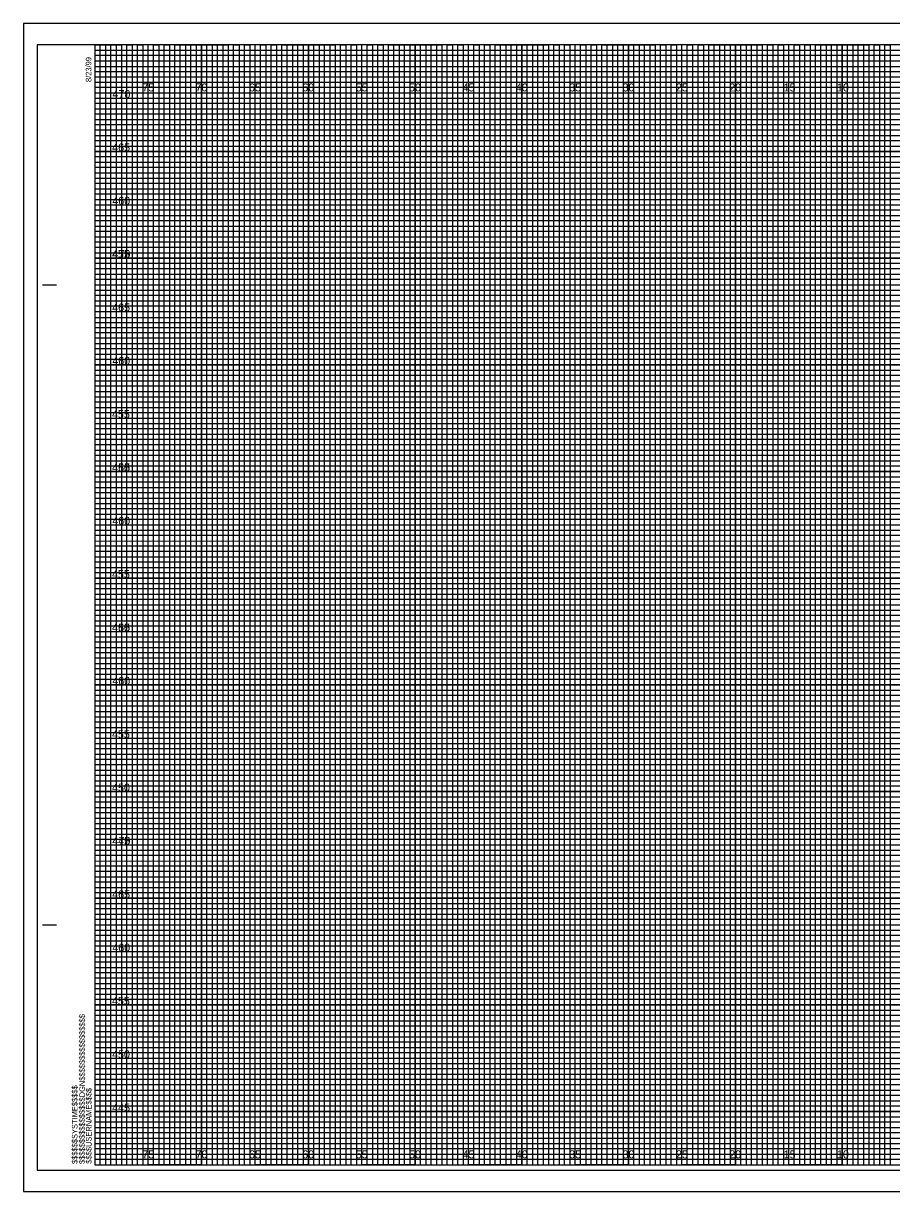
# Model space of a CAD drawing. Extents: x -7 to 162, y 328 to 437.
# Drawn here: x -6.7 to 74.6, y 327.5 to 437 of the extents above; entities that cross this region are included whole.
import ezdxf

# ---------------------------------------------------------------- set-up
doc = ezdxf.new("R2010")
doc.units = 0
for name, color, linetype in [('Prop XS Elevation Labels', 7, 'Continuous'), ('Prop XS Offset Labels', 7, 'Continuous'), ('Sheet Cross Section CELL', 7, 'Continuous'), ('Sheet Cross Section Grid Major CELL', 7, 'Continuous'), ('Sheet Cross Section Grid Middle CELL', 7, 'Continuous'), ('Sheet Cross Section Grid Minor 1 CELL', 7, 'Continuous'), ('Sheet Cross Section Grid Minor 2 CELL', 7, 'Continuous'), ('Sheet Cutting Line CELL', 7, 'Continuous'), ('Sheet DOT Grid CELL', 7, 'Continuous'), ('Sheet Plot Border Inside CELL', 7, 'Continuous'), ('Sheet Plot Border Outside CELL', 7, 'Continuous')]:
    doc.layers.add(name, color=color, linetype=linetype)

msp = doc.modelspace()

# ---------------------------------------------------------------- linework, layer by layer
at = {"layer": 'Sheet Cross Section CELL'}
for p, q in [((-4.9, 412.5), (-3.65, 412.5)), ((-4.85, 412.5), (-3.6, 412.5)), ((-4.9, 352.5), (-3.65, 352.5)), ((-4.85, 352.5), (-3.6, 352.5)), ((0, 330), (0, 330)), ((0, 330), (0, 330)), ((0, 330), (0, 330)), ((0, 330), (0, 330)), ((0, 330), (0, 330)), ((0, 330), (0, 330)), ((0, 330), (0, 330))]:
    msp.add_line(p, q, dxfattribs=at)
msp.add_lwpolyline([(160, 435), (0, 435), (0, 330), (160, 330)], close=True, dxfattribs=at)
at = {"layer": 'Sheet Cross Section Grid Major CELL'}
for p, q in [((5, 435), (0, 435)), ((5, 330), (5, 435)), ((15, 435), (10, 435)), ((10, 435), (10, 330)), ((15, 330), (15, 435)), ((25, 435), (20, 435)), ((20, 435), (20, 330)), ((25, 330), (25, 435)), ((35, 435), (30, 435)), ((30, 435), (30, 330)), ((35, 330), (35, 435)), ((45, 435), (40, 435)), ((40, 435), (40, 330)), ((45, 330), (45, 435)), ((55, 435), (50, 435)), ((50, 435), (50, 330)), ((55, 330), (55, 435)), ((65, 435), (60, 435)), ((60, 435), (60, 330)), ((65, 330), (65, 435)), ((75, 435), (70, 435)), ((70, 435), (70, 330)), ((10, 330), (5, 330)), ((20, 330), (15, 330)), ((30, 330), (25, 330)), ((40, 330), (35, 330)), ((50, 330), (45, 330)), ((60, 330), (55, 330)), ((70, 330), (65, 330))]:
    msp.add_line(p, q, dxfattribs=at)
for points in [[(0, 430), (160, 430), (160, 425), (0, 425)], [(0, 420), (160, 420), (160, 415), (0, 415)], [(0, 410), (160, 410), (160, 405), (0, 405)], [(0, 400), (160, 400), (160, 395), (0, 395)], [(0, 390), (160, 390), (160, 385), (0, 385)], [(0, 380), (160, 380), (160, 375), (0, 375)], [(0, 370), (160, 370), (160, 365), (0, 365)], [(0, 360), (160, 360), (160, 355), (0, 355)], [(0, 350), (160, 350), (160, 345), (0, 345)], [(0, 340), (160, 340), (160, 335), (0, 335)]]:
    msp.add_lwpolyline(points, dxfattribs=at)
at = {"layer": 'Sheet Cross Section Grid Middle CELL'}
for points in [[(0, 435), (2.5, 435), (2.5, 330), (7.5, 330), (7.5, 435), (12.5, 435), (12.5, 330), (17.5, 330), (17.5, 435), (22.5, 435), (22.5, 330), (27.5, 330), (27.5, 435), (32.5, 435), (32.5, 330), (37.5, 330), (37.5, 435), (42.5, 435), (42.5, 330), (47.5, 330), (47.5, 435), (52.5, 435), (52.5, 330), (57.5, 330), (57.5, 435), (62.5, 435), (62.5, 330), (67.5, 330), (67.5, 435), (72.5, 435), (72.5, 330), (77.5, 330)], [(0, 432.5), (137.5, 432.5)], [(0, 422.5), (160, 422.5), (160, 427.5), (0, 427.5)], [(0, 412.5), (160, 412.5), (160, 417.5), (0, 417.5)], [(0, 402.5), (160, 402.5), (160, 407.5), (0, 407.5)], [(0, 392.5), (160, 392.5), (160, 397.5), (0, 397.5)], [(0, 382.5), (160, 382.5), (160, 387.5), (0, 387.5)], [(0, 372.5), (160, 372.5), (160, 377.5), (0, 377.5)], [(0, 362.5), (160, 362.5), (160, 367.5), (0, 367.5)], [(0, 352.5), (160, 352.5), (160, 357.5), (0, 357.5)], [(0, 342.5), (160, 342.5), (160, 347.5), (0, 347.5)], [(0, 332.5), (160, 332.5), (160, 337.5), (0, 337.5)]]:
    msp.add_lwpolyline(points, dxfattribs=at)
at = {"layer": 'Sheet Cross Section Grid Minor 1 CELL'}
for p, q in [((0, 434.5), (130, 434.5)), ((130, 433.99), (0, 433.99)), ((0, 433.99), (0, 433.5)), ((0, 433.5), (130, 433.5)), ((130, 432.94), (0, 432.94)), ((0, 432.94), (0, 432)), ((0, 432), (160, 432))]:
    msp.add_line(p, q, dxfattribs=at)
for points in [[(0, 431.5), (135, 431.5), (160, 431.5), (160, 431), (0, 431)], [(0, 430.5), (160, 430.5), (160, 429.5), (0, 429.5)], [(0, 429), (160, 429), (160, 428.5), (0, 428.49)], [(0, 428), (160, 428), (160, 427), (0, 427)], [(0, 426.5), (160, 426.5), (160, 426), (0, 426)], [(0, 425.5), (160, 425.5), (160, 424.5), (0, 424.5)], [(0, 424), (160, 424), (160, 423.5), (0, 423.5)], [(0, 423), (160, 423), (160, 422), (0, 422)], [(0, 421.5), (160, 421.5), (160, 421), (0, 421)], [(0, 420.5), (160, 420.5), (160, 419.5), (0, 419.5)], [(0, 419), (160, 419), (160, 418.5), (0, 418.5)], [(0, 418), (160, 418), (160, 416.98), (160, 416.5), (160, 416), (0, 416)], [(0, 417), (160, 417), (160, 416.5), (0, 416.5)], [(0, 415.5), (160, 415.5), (160, 414.5), (0, 414.51)], [(0, 414.51), (160, 414.5), (160, 414), (0, 414)], [(0, 413.5), (160, 413.5), (160, 413), (0, 413)], [(0, 412), (160, 412), (160, 411.5), (0, 411.5)], [(0, 411), (160, 411), (160, 410.5), (0, 410.5)], [(-0.04, 409.44), (160, 409.44), (160, 408.94), (-0.04, 408.94)], [(0, 408.5), (160, 408.5), (160, 408), (0, 408)], [(0, 407), (160, 407), (160, 406.5), (0, 406.5)], [(0, 406), (160, 406), (160, 405.5), (0, 405.5)], [(0, 404.5), (160, 404.5), (160, 404), (0, 404)], [(0, 403.5), (160, 403.5), (160, 403), (0, 403)], [(0, 402), (160, 402), (160, 401.5), (0, 401.5)], [(0, 401), (160, 401), (160, 400.5), (0, 400.5)], [(0, 399.5), (160, 399.5), (160, 398.99), (0, 399)], [(0, 398.5), (160, 398.5), (160, 398), (0, 398)], [(0, 397), (160, 397), (160, 396.5), (0, 396.5)], [(0, 396), (160, 396), (160, 395.5), (0, 395.5)], [(0, 394.5), (160, 394.5), (160, 394), (0, 394)], [(0, 393.5), (160, 393.5), (160, 393), (0, 393)], [(0, 392), (160, 392), (160, 391.5), (0, 391.5)], [(0, 391), (160, 391), (160, 390.5), (0, 390.5)], [(0, 389.5), (160, 389.5), (160, 389), (0, 389)], [(0, 388.5), (160.03, 388.45), (160, 388), (0, 388)], [(0, 387), (160, 387), (160, 386.5), (0, 386.5)], [(0, 386), (160, 386), (160, 385.5), (0, 385.5)], [(0, 384.5), (160, 384.5), (160, 384), (0, 384)], [(0, 383.5), (160, 383.5), (160, 383), (0, 383)], [(0, 382), (160, 382), (160, 381.5), (0, 381.5)], [(0, 381), (160, 381), (160, 380.5), (0, 380.5)], [(0, 379.5), (160, 379.5), (160, 379), (0, 379)], [(0, 378.5), (160, 378.5), (160, 378), (0, 378)], [(0, 377), (160, 377), (160, 376.5), (0, 376.5)], [(0, 376), (160, 376), (160, 375.5), (0, 375.5)], [(0, 374.5), (160, 374.5), (160, 374), (0, 374)], [(0, 373.5), (160, 373.5), (160, 373), (0, 373)], [(0, 372), (160, 372), (160, 371.5), (0, 371.5)], [(0, 371), (160, 371), (160, 370.5), (0, 370.5)], [(0, 369.5), (160, 369.5), (160, 368.99), (0, 369)], [(0, 368.5), (160, 368.5), (160, 368), (0, 368)], [(0, 367), (160, 367), (160, 366.5), (0, 366.5)], [(0, 366), (160, 366), (160, 365.5), (0, 365.5)], [(0, 364.5), (160, 364.5), (160, 364), (0, 364)], [(0, 363.5), (160, 363.5), (160, 363), (0, 363)], [(0, 362), (160, 362), (160, 361.5), (0, 361.5)], [(0, 361), (160, 361), (160, 360.5), (0, 360.5)], [(0, 359.5), (160, 359.5), (160, 359), (0, 359)], [(0, 358.5), (160.03, 358.45), (160, 358), (0, 358)], [(0, 357), (160, 357), (160, 356.5), (0, 356.5)], [(0, 356), (160, 356), (160, 355.5), (0, 355.5)], [(0, 354.5), (160, 354.5), (160, 354), (0, 354)], [(0, 353.5), (160, 353.5), (160, 353), (0, 353)], [(0, 352), (160, 352), (160, 351.5), (0, 351.5)], [(0, 351), (160, 351), (160, 350.5), (0, 350.5)], [(0, 349.5), (160, 349.5), (160, 349), (0, 349)], [(0, 348.5), (160, 348.5), (160, 348), (0, 348)], [(0, 347), (160, 347), (160, 346.5), (0, 346.5)], [(0, 346), (160, 346), (160, 345.5), (0, 345.5)], [(0, 344.5), (160, 344.5), (160, 344), (0, 344)], [(0, 343.5), (160, 343.5), (160, 343), (0, 343)], [(0, 342), (160, 342), (160, 341.5), (0, 341.5)], [(0, 341), (160, 341), (160, 340.5), (0, 340.5)], [(0, 339.5), (160, 339.5), (160, 339), (0, 339)], [(0, 338.5), (160, 338.5), (160, 338), (0, 338)], [(0, 337), (160, 337), (160, 336.5), (0, 336.5)], [(0, 336), (160, 336), (160, 335.5), (0, 335.5)], [(0, 334.5), (160, 334.5), (160, 334), (0, 334)], [(0, 333.5), (160, 333.5), (160, 333), (0, 333)], [(0, 332), (160, 332), (160, 331.5), (0, 331.5)], [(0, 331), (160, 331), (160, 330.5), (0, 330.5)]]:
    msp.add_lwpolyline(points, dxfattribs=at)
at = {"layer": 'Sheet Cross Section Grid Minor 2 CELL'}
for points in [[(0, 330), (0.5, 330), (0.5, 435), (1, 435), (1, 330)], [(1, 330), (1.5, 330), (1.5, 435), (2, 435), (2, 330)], [(2.5, 330), (3, 330), (3, 435), (3.5, 435), (3.5, 330)], [(3.5, 330), (4, 330), (4, 435), (4.5, 435), (4.5, 330)], [(5, 330), (5.5, 330), (5.5, 435), (6, 435), (6, 330)], [(6, 330), (6.5, 330), (6.5, 435), (7, 435), (7, 330)], [(7.5, 330), (8, 330), (8, 435), (8.5, 435), (8.5, 330)], [(8.5, 330), (9, 330), (9, 435), (9.5, 435), (9.5, 330)], [(10, 330), (10.5, 330), (10.5, 435), (11, 435), (11, 330)], [(11, 330), (11.5, 330), (11.5, 435), (12, 435), (12, 330)], [(12.5, 330), (13, 330), (13, 435), (13.5, 435), (13.5, 330)], [(13.5, 330), (14, 330), (14, 435), (14.5, 435), (14.5, 330)], [(15, 330), (15.5, 330), (15.5, 435), (16, 435), (16, 330)], [(16, 330), (16.5, 330), (16.5, 435), (17, 435), (17, 330)], [(17.5, 330), (18, 330), (18, 435), (18.5, 435), (18.5, 330)], [(18.5, 330), (19, 330), (19, 435), (19.5, 435), (19.5, 330)], [(20, 330), (20.5, 330), (20.5, 435), (21, 435), (21, 330)], [(21, 330), (21.5, 330), (21.5, 435), (22, 435), (22, 330)], [(22.5, 330), (23, 330), (23, 435), (23.5, 435), (23.5, 330)], [(23.5, 330), (24, 330), (24, 435), (24.5, 435), (24.5, 330)], [(25, 330), (25.5, 330), (25.5, 435), (26, 435), (26, 330)], [(26, 330), (26.5, 330), (26.5, 435), (27, 435), (27, 330)], [(27.5, 330), (28, 330), (28, 435), (28.5, 435), (28.5, 330)], [(28.5, 330), (29, 330), (29, 435), (29.5, 435), (29.5, 330)], [(30, 330), (30.5, 330), (30.5, 435), (31, 435), (31, 330)], [(31, 330), (31.5, 330), (31.5, 435), (32, 435), (32, 330)], [(32.5, 330), (33, 330), (33, 435), (33.5, 435), (33.5, 330)], [(33.5, 330), (34, 330), (34, 435), (34.5, 435), (34.5, 330)], [(35, 330), (35.5, 330), (35.5, 435), (36, 435), (36, 330)], [(36, 330), (36.5, 330), (36.5, 435), (37, 435), (37, 330)], [(37.5, 330), (38, 330), (38, 435), (38.5, 435), (38.5, 330)], [(38.5, 330), (39, 330), (39, 435), (39.5, 435), (39.5, 330)], [(40, 330), (40.5, 330), (40.5, 435), (41, 435), (41, 330)], [(41, 330), (41.5, 330), (41.5, 435), (42, 435), (42, 330)], [(42.5, 330), (43, 330), (43, 435), (43.5, 435), (43.5, 330)], [(43.5, 330), (44, 330), (44, 435), (44.5, 435), (44.5, 330)], [(45, 330), (45.5, 330), (45.5, 435), (46, 435), (46, 330)], [(46, 330), (46.5, 330), (46.5, 435), (47, 435), (47, 330)], [(47.5, 330), (48, 330), (48, 435), (48.5, 435), (48.5, 330)], [(48.5, 330), (49, 330), (49, 435), (49.5, 435), (49.5, 330)], [(50, 330), (50.5, 330), (50.5, 435), (51, 435), (51, 330)], [(51, 330), (51.5, 330), (51.5, 435), (52, 435), (52, 330)], [(52.5, 330), (53, 330), (53, 435), (53.5, 435), (53.5, 330)], [(53.5, 330), (54, 330), (54, 435), (54.5, 435), (54.5, 330)], [(55, 330), (55.5, 330), (55.5, 435), (56, 435), (56, 330)], [(56, 330), (56.5, 330), (56.5, 435), (57, 435), (57, 330)], [(57.5, 330), (58, 330), (58, 435), (58.5, 435), (58.5, 330)], [(58.5, 330), (59, 330), (59, 435), (59.5, 435), (59.5, 330)], [(60, 330), (60.5, 330), (60.5, 435), (61, 435), (61, 330)], [(61, 330), (61.5, 330), (61.5, 435), (62, 435), (62, 330)], [(62.5, 330), (63, 330), (63, 435), (63.5, 435), (63.5, 330)], [(63.5, 330), (64, 330), (64, 435), (64.5, 435), (64.5, 330)], [(65, 330), (65.5, 330), (65.5, 435), (66, 435), (66, 330)], [(66, 330), (66.5, 330), (66.5, 435), (67, 435), (67, 330)], [(67.5, 330), (68, 330), (68, 435), (68.5, 435), (68.5, 330)], [(68.5, 330), (69, 330), (69, 435), (69.5, 435), (69.5, 330)], [(70, 330), (70.5, 330), (70.5, 435), (71, 435), (71, 330)], [(71, 330), (71.5, 330), (71.5, 435), (72, 435), (72, 330)], [(72.5, 330), (73, 330), (73, 435), (73.5, 435), (73.5, 330)], [(73.5, 330), (74, 330), (74, 435), (74.5, 435), (74.5, 330)]]:
    msp.add_lwpolyline(points, dxfattribs=at)
at = {"layer": 'Sheet Cutting Line CELL'}
for p, q in [((161.65, 437), (-6.7, 437)), ((-6.7, 437), (-6.7, 327.5)), ((-6.7, 327.5), (161.65, 327.5))]:
    msp.add_line(p, q, dxfattribs=at)
at = {"layer": 'Sheet DOT Grid CELL'}
for p, q in [((5, 330), (5, 435)), ((10, 330), (10, 435)), ((15, 330), (15, 435)), ((20, 330), (20, 435)), ((25, 330), (25, 435)), ((30, 330), (30, 435)), ((35, 330), (35, 435)), ((40, 330), (40, 435)), ((45, 330), (45, 435)), ((50, 330), (50, 435)), ((55, 330), (55, 435)), ((60, 330), (60, 435)), ((65, 330), (65, 435)), ((70, 330), (70, 435)), ((0, 430), (160, 430)), ((0, 425), (160, 425)), ((0, 420), (160, 420)), ((0, 415), (160, 415)), ((0, 410), (160, 410)), ((0, 405), (160, 405)), ((0, 400), (160, 400)), ((0, 395), (160, 395)), ((0, 390), (160, 390)), ((0, 385), (160, 385)), ((0, 380), (160, 380)), ((0, 375), (160, 375)), ((0, 370), (160, 370)), ((0, 365), (160, 365)), ((0, 360), (160, 360)), ((0, 355), (160, 355)), ((0, 350), (160, 350)), ((0, 345), (160, 345)), ((0, 340), (160, 340)), ((0, 335), (160, 335))]:
    msp.add_line(p, q, dxfattribs=at)
at = {"layer": 'Sheet Plot Border Inside CELL'}
msp.add_lwpolyline([(-5.4, 329.5), (161.2, 329.5), (161.2, 435), (-5.4, 435)], close=True, dxfattribs=at)
at = {"layer": 'Sheet Plot Border Outside CELL'}
msp.add_lwpolyline([(-6.7, 327.5), (161.65, 327.5), (161.65, 437), (-6.7, 437)], close=True, dxfattribs=at)

# ---------------------------------------------------------------- texts
at = {"layer": 'Prop XS Elevation Labels'}
for s, p in [('470', (1.65, 430)), ('465', (1.62, 425)), ('460', (1.63, 420)), ('455', (1.6, 415)), ('470', (1.65, 415)), ('465', (1.62, 410)), ('460', (1.63, 405)), ('455', (1.6, 400)), ('450', (1.61, 395)), ('465', (1.62, 395)), ('460', (1.63, 390)), ('455', (1.6, 385)), ('450', (1.61, 380)), ('465', (1.62, 380)), ('460', (1.63, 375)), ('455', (1.6, 370)), ('450', (1.61, 365)), ('445', (1.62, 360)), ('470', (1.65, 360)), ('465', (1.62, 355)), ('460', (1.63, 350)), ('455', (1.6, 345)), ('450', (1.61, 340)), ('445', (1.62, 335))]:
    msp.add_text(s, height=0.75, dxfattribs=at).set_placement(p)
at = {"layer": 'Prop XS Offset Labels'}
for s, p in [('75', (4.44, 430.62)), ('70', (9.43, 430.62)), ('65', (14.44, 430.62)), ('60', (19.43, 430.62)), ('55', (24.44, 430.62)), ('50', (29.43, 430.62)), ('45', (34.44, 430.62)), ('40', (39.43, 430.62)), ('35', (44.44, 430.62)), ('30', (49.43, 430.62)), ('25', (54.44, 430.62)), ('20', (59.43, 430.62)), ('15', (64.53, 430.62)), ('10', (69.52, 430.62)), ('75', (4.44, 330.62)), ('70', (9.43, 330.62)), ('65', (14.44, 330.62)), ('60', (19.43, 330.62)), ('55', (24.44, 330.62)), ('50', (29.43, 330.62)), ('45', (34.44, 330.62)), ('40', (39.43, 330.62)), ('35', (44.44, 330.62)), ('30', (49.43, 330.62)), ('25', (54.44, 330.62)), ('20', (59.43, 330.62)), ('15', (64.53, 330.62)), ('10', (69.52, 330.62))]:
    msp.add_text(s, height=0.75, dxfattribs=at).set_placement(p)
at = {"layer": 'Sheet Cross Section CELL'}
for s, p in [('8/23/99', (-0.33, 431.5)), ('$$$$$$$$$$$$$$$$DGN$$$$$$$$$$$$$$$$', (-0.94, 330.09)), ('$$$$$$SYSTIME$$$$$', (-1.63, 330.09)), ('$$$$USERNAME$$$$', (-0.31, 330.12))]:
    msp.add_text(s, height=0.525, rotation=90, dxfattribs=at).set_placement(p)

doc.saveas('drawing.dxf')
